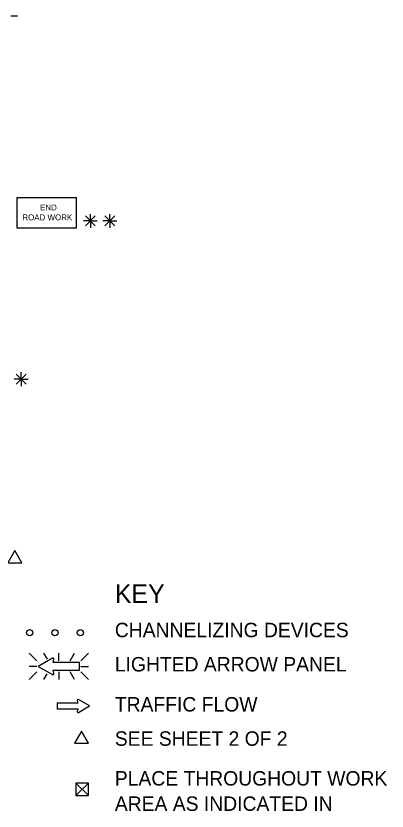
# Model space of a CAD drawing. Extents: x 16440 to 18464, y 5737 to 6974.
# Drawn here: x 17191 to 17430, y 6400 to 6911 of the extents above; entities that cross this region are included whole.
import ezdxf

# ---------------------------------------------------------------- set-up
doc = ezdxf.new("R2010")
doc.units = 0
for name, color, linetype in [('MT_SCRATCH_LEVEL_E', 7, 'Continuous'), ('TRAFFIC_SIGNS_PR', 7, 'Continuous'), ('TYPICAL_TEXT_DIMEN_EX', 7, 'Continuous'), ('TYPICAL_TEXT_DIMEN_PR', 7, 'Continuous')]:
    doc.layers.add(name, color=color, linetype=linetype)

msp = doc.modelspace()

# ---------------------------------------------------------------- linework, layer by layer
at = {"layer": 'MT_SCRATCH_LEVEL_E'}
for p, q in [((17238.65, 6467.22), (17231.41, 6471.33)), ((17231.04, 6469.07), (17217.79, 6469.07)), ((17217.79, 6469.07), (17217.79, 6465.33)), ((17230.73, 6470.85), (17231.04, 6469.07)), ((17231.41, 6463.07), (17238.65, 6467.22)), ((17217.79, 6465.33), (17231.04, 6465.33)), ((17231.04, 6465.33), (17230.73, 6463.55))]:
    msp.add_line(p, q, dxfattribs=at)
for centre, start, end in [((17231.19, 6470.93), 60.4248, 189.9638), ((17231.19, 6463.48), 170.0362, 299.7731)]:
    msp.add_arc(centre, 0.463, start, end, dxfattribs=at)
at = {"layer": 'TRAFFIC_SIGNS_PR'}
for p, q in [((17199.72, 6501.23), (17204.65, 6496.3)), ((17211.48, 6497.41), (17209.27, 6501.23)), ((17218.8, 6496.3), (17218.8, 6501.23)), ((17226.04, 6496.3), (17228.89, 6501.23)), ((17232.95, 6496.3), (17237.89, 6501.23)), ((17204.65, 6492.74), (17199.72, 6492.74)), ((17232.95, 6492.74), (17237.89, 6492.74)), ((17199.72, 6484.25), (17204.65, 6489.19)), ((17209.23, 6484.25), (17211.34, 6487.91)), ((17218.8, 6489.19), (17218.8, 6484.25)), ((17228.93, 6484.25), (17226.08, 6489.19)), ((17232.95, 6489.19), (17237.89, 6484.25))]:
    msp.add_line(p, q, dxfattribs=at)
msp.add_lwpolyline([(17191.72, 6775.12), (17230.12, 6775.12), (17230.12, 6794.32), (17191.72, 6794.32)], close=True, dxfattribs=at)
for points in [[(17214.73, 6498.02), (17205.44, 6492.74), (17214.73, 6487.42)], [(17215.6, 6488.05), (17215.2, 6490.32), (17232.22, 6490.32), (17232.22, 6495.12), (17215.2, 6495.12), (17215.61, 6497.4)]]:
    msp.add_lwpolyline(points, dxfattribs=at)
for centre in [(17200.06, 6514.43), (17216.36, 6514.43), (17232.66, 6514.43)]:
    msp.add_circle(centre, 2, dxfattribs=at)
for centre, radius, start, end in [((17215.02, 6497.49), 0.598, 350.7308, 118.8916), ((17215.02, 6487.94), 0.597, 241.4833, 9.9593)]:
    msp.add_arc(centre, radius, start, end, dxfattribs=at)
at = {"layer": 'TYPICAL_TEXT_DIMEN_PR'}
for p, q in [((17187.83, 6911.5), (17192.31, 6911.5)), ((17239.15, 6779.49), (17239.15, 6783.94)), ((17251.7, 6779.49), (17251.7, 6783.94)), ((17239.15, 6779.49), (17234.62, 6779.49)), ((17235.96, 6782.68), (17242.33, 6776.3)), ((17242.33, 6782.68), (17235.96, 6776.3)), ((17239.15, 6779.49), (17242.33, 6779.49)), ((17239.15, 6779.49), (17243.62, 6779.49)), ((17239.15, 6779.49), (17239.15, 6774.99)), ((17251.7, 6779.49), (17247.17, 6779.49)), ((17254.89, 6782.68), (17248.51, 6776.3)), ((17248.52, 6782.68), (17254.89, 6776.3)), ((17251.7, 6779.49), (17254.89, 6779.49)), ((17251.7, 6779.49), (17256.18, 6779.49)), ((17251.7, 6779.49), (17251.7, 6774.99)), ((17194.54, 6677.57), (17194.54, 6682.03)), ((17194.54, 6677.57), (17190.01, 6677.57)), ((17191.35, 6680.76), (17197.72, 6674.38)), ((17197.72, 6680.76), (17191.35, 6674.38)), ((17194.54, 6677.57), (17197.72, 6677.57)), ((17194.54, 6677.57), (17199.01, 6677.57)), ((17194.54, 6677.57), (17194.54, 6673.07)), ((17229.89, 6417.48), (17237.89, 6409.48)), ((17229.89, 6409.48), (17237.89, 6417.48))]:
    msp.add_line(p, q, dxfattribs=at)
for points in [[(17190.44, 6567.27), (17185.92, 6559.44), (17194.97, 6559.44)], [(17233.36, 6451.05), (17228.84, 6443.21), (17237.89, 6443.21)], [(17229.89, 6417.48), (17229.89, 6409.48), (17237.89, 6409.48), (17237.89, 6417.48)]]:
    msp.add_lwpolyline(points, close=True, dxfattribs=at)

# ---------------------------------------------------------------- texts
at = {"layer": 'TRAFFIC_SIGNS_PR'}
for s, p in [('END', (17206.73, 6786.24)), ('ROAD WORK', (17195.33, 6779.86))]:
    msp.add_text(s, height=3.831, dxfattribs=at).set_placement(p)
at = {"layer": 'TYPICAL_TEXT_DIMEN_EX'}
for s, height, p in [('KEY', 12, (17254.9, 6533.54)), ('CHANNELIZING DEVICES', 9.3, (17254.9, 6511.49)), ('LIGHTED ARROW PANEL', 9.3, (17254.9, 6489.44)), ('TRAFFIC FLOW', 9.3, (17254.9, 6463.64)), ('SEE SHEET 2 OF 2', 9.3, (17254.9, 6441.59)), ('PLACE THROUGHOUT WORK', 9.3, (17254.9, 6415.98)), ('AREA AS INDICATED IN', 9.3, (17254.9, 6399.68))]:
    msp.add_text(s, height=height, dxfattribs=at).set_placement(p)

doc.saveas('drawing.dxf')
